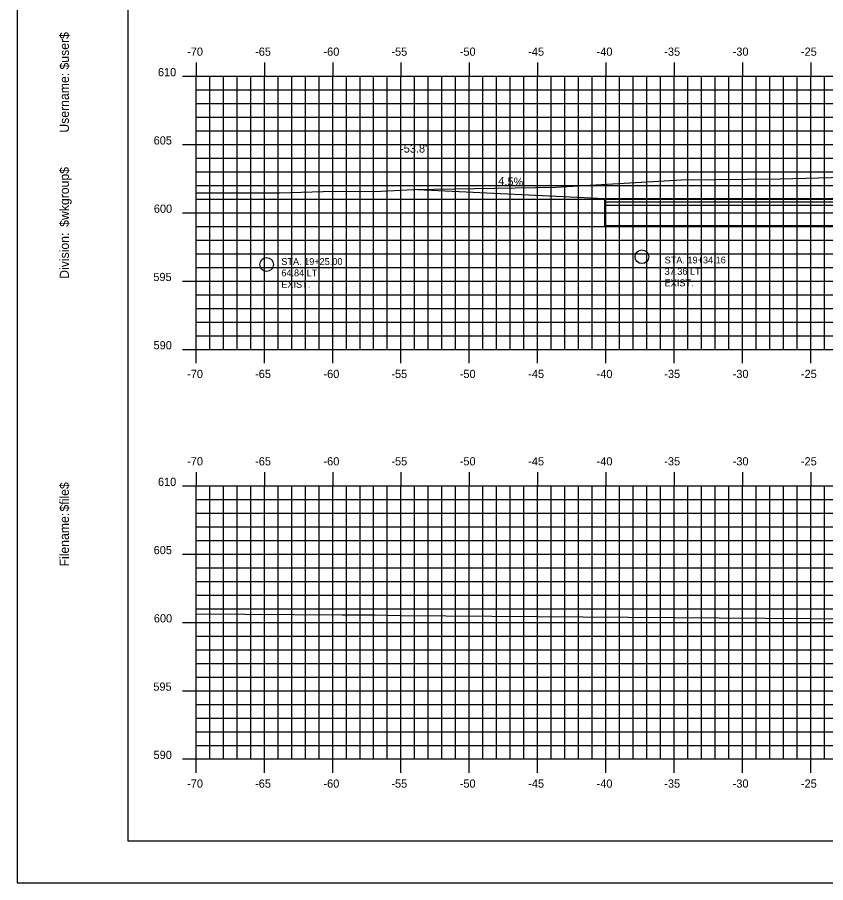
# Model space of a CAD drawing. Extents: x 1048141 to 1048311, y 780904 to 781014.
# Drawn here: x 1048140.6 to 1048199.8, y 780904.1 to 780967.4 of the extents above; entities that cross this region are included whole.
import ezdxf

# ---------------------------------------------------------------- set-up
doc = ezdxf.new("R2010")
doc.units = 0
for name, color, linetype in [('ANNOTATION', 7, 'Continuous'), ('D_Roadway_Centerline', 7, 'Continuous'), ('D_Roadway_Edge_Pavement', 7, 'Continuous'), ('D_Roadway_Pavement', 7, 'Continuous'), ('D_Roadway_SlopeLines', 7, 'Continuous'), ('D_Roadway_SubGrade', 7, 'Continuous'), ('D_Text_Monospaced', 7, 'Continuous'), ('Default', 7, 'Continuous'), ('H_V ANNOTATION', 7, 'Continuous'), ('MAJOR', 7, 'Continuous'), ('MINOR', 7, 'Continuous'), ('S_Roadway_Centerline', 7, 'Continuous'), ('S_Utilities_UG_Water_Line', 7, 'Continuous')]:
    doc.layers.add(name, color=color, linetype=linetype)

msp = doc.modelspace()

# ---------------------------------------------------------------- linework, layer by layer
at = {"layer": 'D_Roadway_Centerline'}
msp.add_line((1048183.644, 780954.167), (1048183.644, 780954.167), dxfattribs=at)
msp.add_lwpolyline([(1048169.913, 780954.819), (1048183.644, 780954.167), (1048223.713, 780954.151), (1048293.713, 780953.171)], dxfattribs=at)
at = {"layer": 'D_Roadway_Edge_Pavement'}
msp.add_lwpolyline([(1048183.644, 780953.917), (1048183.644, 780954.167), (1048223.713, 780954.151), (1048293.713, 780953.171), (1048293.709, 780952.921), (1048223.713, 780953.901)], close=True, dxfattribs=at)
at = {"layer": 'D_Roadway_Pavement'}
msp.add_lwpolyline([(1048183.644, 780953.667), (1048183.644, 780953.917), (1048223.713, 780953.901), (1048293.709, 780952.921), (1048293.706, 780952.671), (1048223.713, 780953.651)], close=True, dxfattribs=at)
at = {"layer": 'D_Roadway_SlopeLines'}
msp.add_line((1048183.644, 780954.167), (1048183.644, 780954.167), dxfattribs=at)
at = {"layer": 'D_Roadway_SubGrade'}
msp.add_lwpolyline([(1048183.644, 780952.167), (1048183.644, 780953.667), (1048223.713, 780953.651), (1048293.706, 780952.671), (1048293.685, 780951.171), (1048223.713, 780952.151)], close=True, dxfattribs=at)
at = {"layer": 'Default'}
for p, q in [((1048148.713, 781012.114), (1048148.713, 780907.114)), ((1048223.712, 780952.151), (1048183.643, 780952.167)), ((1048148.713, 780907.114), (1048308.713, 780907.114))]:
    msp.add_line(p, q, dxfattribs=at)
msp.add_lwpolyline([(1048140.62, 780904.055), (1048310.62, 780904.055), (1048310.62, 781014.055), (1048140.62, 781014.055)], close=True, dxfattribs=at)
at = {"layer": 'MAJOR'}
for p, q in [((1048153.713, 780964.116), (1048153.713, 780963.114)), ((1048158.713, 780964.116), (1048158.713, 780963.114)), ((1048163.713, 780964.116), (1048163.713, 780963.114)), ((1048168.713, 780964.116), (1048168.713, 780963.114)), ((1048173.713, 780964.116), (1048173.713, 780963.114)), ((1048178.713, 780964.116), (1048178.713, 780963.114)), ((1048183.713, 780964.116), (1048183.713, 780963.114)), ((1048188.713, 780964.116), (1048188.713, 780963.114)), ((1048193.713, 780964.116), (1048193.713, 780963.114)), ((1048198.713, 780964.116), (1048198.713, 780963.114)), ((1048152.711, 780963.114), (1048153.713, 780963.114)), ((1048153.713, 780963.114), (1048293.713, 780963.114)), ((1048153.713, 780943.114), (1048153.713, 780963.114)), ((1048153.713, 780943.114), (1048153.713, 780963.114)), ((1048153.713, 780963.114), (1048293.713, 780963.114)), ((1048158.713, 780943.114), (1048158.713, 780963.114)), ((1048163.713, 780943.114), (1048163.713, 780963.114)), ((1048168.713, 780943.114), (1048168.713, 780963.114)), ((1048173.713, 780943.114), (1048173.713, 780963.114)), ((1048178.713, 780943.114), (1048178.713, 780963.114)), ((1048183.713, 780943.114), (1048183.713, 780963.114)), ((1048188.713, 780943.114), (1048188.713, 780963.114)), ((1048193.713, 780943.114), (1048193.713, 780963.114)), ((1048198.713, 780943.114), (1048198.713, 780963.114)), ((1048152.711, 780958.114), (1048153.713, 780958.114)), ((1048153.713, 780958.114), (1048293.713, 780958.114)), ((1048152.711, 780953.114), (1048153.713, 780953.114)), ((1048153.713, 780953.114), (1048293.713, 780953.114)), ((1048152.711, 780948.114), (1048153.713, 780948.114)), ((1048153.713, 780948.114), (1048293.713, 780948.114)), ((1048152.711, 780943.114), (1048153.713, 780943.114)), ((1048153.713, 780943.114), (1048293.713, 780943.114)), ((1048153.713, 780943.114), (1048293.713, 780943.114)), ((1048153.713, 780942.112), (1048153.713, 780943.114)), ((1048158.713, 780942.112), (1048158.713, 780943.114)), ((1048163.713, 780942.112), (1048163.713, 780943.114)), ((1048168.713, 780942.112), (1048168.713, 780943.114)), ((1048173.713, 780942.112), (1048173.713, 780943.114)), ((1048178.713, 780942.112), (1048178.713, 780943.114)), ((1048183.713, 780942.112), (1048183.713, 780943.114)), ((1048188.713, 780942.112), (1048188.713, 780943.114)), ((1048193.713, 780942.112), (1048193.713, 780943.114)), ((1048198.713, 780942.112), (1048198.713, 780943.114)), ((1048153.713, 780934.116), (1048153.713, 780933.114)), ((1048158.713, 780934.116), (1048158.713, 780933.114)), ((1048163.713, 780934.116), (1048163.713, 780933.114)), ((1048168.713, 780934.116), (1048168.713, 780933.114)), ((1048173.713, 780934.116), (1048173.713, 780933.114)), ((1048178.713, 780934.116), (1048178.713, 780933.114)), ((1048183.713, 780934.116), (1048183.713, 780933.114)), ((1048188.713, 780934.116), (1048188.713, 780933.114)), ((1048193.713, 780934.116), (1048193.713, 780933.114)), ((1048198.713, 780934.116), (1048198.713, 780933.114)), ((1048152.711, 780933.114), (1048153.713, 780933.114)), ((1048153.713, 780933.114), (1048293.713, 780933.114)), ((1048153.713, 780913.114), (1048153.713, 780933.114)), ((1048153.713, 780913.114), (1048153.713, 780933.114)), ((1048153.713, 780933.114), (1048293.713, 780933.114)), ((1048158.713, 780913.114), (1048158.713, 780933.114)), ((1048163.713, 780913.114), (1048163.713, 780933.114)), ((1048168.713, 780913.114), (1048168.713, 780933.114)), ((1048173.713, 780913.114), (1048173.713, 780933.114)), ((1048178.713, 780913.114), (1048178.713, 780933.114)), ((1048183.713, 780913.114), (1048183.713, 780933.114)), ((1048188.713, 780913.114), (1048188.713, 780933.114)), ((1048193.713, 780913.114), (1048193.713, 780933.114)), ((1048198.713, 780913.114), (1048198.713, 780933.114)), ((1048152.711, 780928.114), (1048153.713, 780928.114)), ((1048153.713, 780928.114), (1048293.713, 780928.114)), ((1048152.711, 780923.114), (1048153.713, 780923.114)), ((1048153.713, 780923.114), (1048293.713, 780923.114)), ((1048152.711, 780918.114), (1048153.713, 780918.114)), ((1048153.713, 780918.114), (1048293.713, 780918.114)), ((1048152.711, 780913.114), (1048153.713, 780913.114)), ((1048153.713, 780913.114), (1048293.713, 780913.114)), ((1048153.713, 780913.114), (1048293.713, 780913.114)), ((1048153.713, 780912.112), (1048153.713, 780913.114)), ((1048158.713, 780912.112), (1048158.713, 780913.114)), ((1048163.713, 780912.112), (1048163.713, 780913.114)), ((1048168.713, 780912.112), (1048168.713, 780913.114)), ((1048173.713, 780912.112), (1048173.713, 780913.114)), ((1048178.713, 780912.112), (1048178.713, 780913.114)), ((1048183.713, 780912.112), (1048183.713, 780913.114)), ((1048188.713, 780912.112), (1048188.713, 780913.114)), ((1048193.713, 780912.112), (1048193.713, 780913.114)), ((1048198.713, 780912.112), (1048198.713, 780913.114))]:
    msp.add_line(p, q, dxfattribs=at)
at = {"layer": 'MINOR'}
for p, q in [((1048154.713, 780943.114), (1048154.713, 780963.114)), ((1048155.713, 780943.114), (1048155.713, 780963.114)), ((1048156.713, 780943.114), (1048156.713, 780963.114)), ((1048157.713, 780943.114), (1048157.713, 780963.114)), ((1048159.713, 780943.114), (1048159.713, 780963.114)), ((1048160.713, 780943.114), (1048160.713, 780963.114)), ((1048161.713, 780943.114), (1048161.713, 780963.114)), ((1048162.713, 780943.114), (1048162.713, 780963.114)), ((1048164.713, 780943.114), (1048164.713, 780963.114)), ((1048165.713, 780943.114), (1048165.713, 780963.114)), ((1048166.713, 780943.114), (1048166.713, 780963.114)), ((1048167.713, 780943.114), (1048167.713, 780963.114)), ((1048169.713, 780943.114), (1048169.713, 780963.114)), ((1048170.713, 780943.114), (1048170.713, 780963.114)), ((1048171.713, 780943.114), (1048171.713, 780963.114)), ((1048172.713, 780943.114), (1048172.713, 780963.114)), ((1048174.713, 780943.114), (1048174.713, 780963.114)), ((1048175.713, 780943.114), (1048175.713, 780963.114)), ((1048176.713, 780943.114), (1048176.713, 780963.114)), ((1048177.713, 780943.114), (1048177.713, 780963.114)), ((1048179.713, 780943.114), (1048179.713, 780963.114)), ((1048180.713, 780943.114), (1048180.713, 780963.114)), ((1048181.713, 780943.114), (1048181.713, 780963.114)), ((1048182.713, 780943.114), (1048182.713, 780963.114)), ((1048184.713, 780943.114), (1048184.713, 780963.114)), ((1048185.713, 780943.114), (1048185.713, 780963.114)), ((1048186.713, 780943.114), (1048186.713, 780963.114)), ((1048187.713, 780943.114), (1048187.713, 780963.114)), ((1048189.713, 780943.114), (1048189.713, 780963.114)), ((1048190.713, 780943.114), (1048190.713, 780963.114)), ((1048191.713, 780943.114), (1048191.713, 780963.114)), ((1048192.713, 780943.114), (1048192.713, 780963.114)), ((1048194.713, 780943.114), (1048194.713, 780963.114)), ((1048195.713, 780943.114), (1048195.713, 780963.114)), ((1048196.713, 780943.114), (1048196.713, 780963.114)), ((1048197.713, 780943.114), (1048197.713, 780963.114)), ((1048199.713, 780943.114), (1048199.713, 780963.114)), ((1048153.713, 780962.114), (1048293.713, 780962.114)), ((1048153.713, 780962.114), (1048154.715, 780962.114)), ((1048153.713, 780961.114), (1048293.713, 780961.114)), ((1048153.713, 780961.114), (1048154.715, 780961.114)), ((1048153.713, 780960.114), (1048293.713, 780960.114)), ((1048153.713, 780960.114), (1048154.715, 780960.114)), ((1048153.713, 780959.114), (1048293.713, 780959.114)), ((1048153.713, 780959.114), (1048154.715, 780959.114)), ((1048153.713, 780957.114), (1048293.713, 780957.114)), ((1048153.713, 780957.114), (1048154.715, 780957.114)), ((1048153.713, 780956.114), (1048293.713, 780956.114)), ((1048153.713, 780956.114), (1048154.715, 780956.114)), ((1048153.713, 780955.114), (1048293.713, 780955.114)), ((1048153.713, 780955.114), (1048154.715, 780955.114)), ((1048153.713, 780954.114), (1048293.713, 780954.114)), ((1048153.713, 780954.114), (1048154.715, 780954.114)), ((1048153.713, 780952.114), (1048293.713, 780952.114)), ((1048153.713, 780952.114), (1048154.715, 780952.114)), ((1048153.713, 780951.114), (1048293.713, 780951.114)), ((1048153.713, 780951.114), (1048154.715, 780951.114)), ((1048153.713, 780950.114), (1048293.713, 780950.114)), ((1048153.713, 780950.114), (1048154.715, 780950.114)), ((1048153.713, 780949.114), (1048293.713, 780949.114)), ((1048153.713, 780949.114), (1048154.715, 780949.114)), ((1048153.713, 780947.114), (1048293.713, 780947.114)), ((1048153.713, 780947.114), (1048154.715, 780947.114)), ((1048153.713, 780946.114), (1048293.713, 780946.114)), ((1048153.713, 780946.114), (1048154.715, 780946.114)), ((1048153.713, 780945.114), (1048293.713, 780945.114)), ((1048153.713, 780945.114), (1048154.715, 780945.114)), ((1048153.713, 780944.114), (1048293.713, 780944.114)), ((1048153.713, 780944.114), (1048154.715, 780944.114)), ((1048154.713, 780913.114), (1048154.713, 780933.114)), ((1048155.713, 780913.114), (1048155.713, 780933.114)), ((1048156.713, 780913.114), (1048156.713, 780933.114)), ((1048157.713, 780913.114), (1048157.713, 780933.114)), ((1048159.713, 780913.114), (1048159.713, 780933.114)), ((1048160.713, 780913.114), (1048160.713, 780933.114)), ((1048161.713, 780913.114), (1048161.713, 780933.114)), ((1048162.713, 780913.114), (1048162.713, 780933.114)), ((1048164.713, 780913.114), (1048164.713, 780933.114)), ((1048165.713, 780913.114), (1048165.713, 780933.114)), ((1048166.713, 780913.114), (1048166.713, 780933.114)), ((1048167.713, 780913.114), (1048167.713, 780933.114)), ((1048169.713, 780913.114), (1048169.713, 780933.114)), ((1048170.713, 780913.114), (1048170.713, 780933.114)), ((1048171.713, 780913.114), (1048171.713, 780933.114)), ((1048172.713, 780913.114), (1048172.713, 780933.114)), ((1048174.713, 780913.114), (1048174.713, 780933.114)), ((1048175.713, 780913.114), (1048175.713, 780933.114)), ((1048176.713, 780913.114), (1048176.713, 780933.114)), ((1048177.713, 780913.114), (1048177.713, 780933.114)), ((1048179.713, 780913.114), (1048179.713, 780933.114)), ((1048180.713, 780913.114), (1048180.713, 780933.114)), ((1048181.713, 780913.114), (1048181.713, 780933.114)), ((1048182.713, 780913.114), (1048182.713, 780933.114)), ((1048184.713, 780913.114), (1048184.713, 780933.114)), ((1048185.713, 780913.114), (1048185.713, 780933.114)), ((1048186.713, 780913.114), (1048186.713, 780933.114)), ((1048187.713, 780913.114), (1048187.713, 780933.114)), ((1048189.713, 780913.114), (1048189.713, 780933.114)), ((1048190.713, 780913.114), (1048190.713, 780933.114)), ((1048191.713, 780913.114), (1048191.713, 780933.114)), ((1048192.713, 780913.114), (1048192.713, 780933.114)), ((1048194.713, 780913.114), (1048194.713, 780933.114)), ((1048195.713, 780913.114), (1048195.713, 780933.114)), ((1048196.713, 780913.114), (1048196.713, 780933.114)), ((1048197.713, 780913.114), (1048197.713, 780933.114)), ((1048199.713, 780913.114), (1048199.713, 780933.114)), ((1048153.713, 780932.114), (1048293.713, 780932.114)), ((1048153.713, 780932.114), (1048154.715, 780932.114)), ((1048153.713, 780931.114), (1048293.713, 780931.114)), ((1048153.713, 780931.114), (1048154.715, 780931.114)), ((1048153.713, 780930.114), (1048293.713, 780930.114)), ((1048153.713, 780930.114), (1048154.715, 780930.114)), ((1048153.713, 780929.114), (1048293.713, 780929.114)), ((1048153.713, 780929.114), (1048154.715, 780929.114)), ((1048153.713, 780927.114), (1048293.713, 780927.114)), ((1048153.713, 780927.114), (1048154.715, 780927.114)), ((1048153.713, 780926.114), (1048293.713, 780926.114)), ((1048153.713, 780926.114), (1048154.715, 780926.114)), ((1048153.713, 780925.114), (1048293.713, 780925.114)), ((1048153.713, 780925.114), (1048154.715, 780925.114)), ((1048153.713, 780924.114), (1048293.713, 780924.114)), ((1048153.713, 780924.114), (1048154.715, 780924.114)), ((1048153.713, 780922.114), (1048293.713, 780922.114)), ((1048153.713, 780922.114), (1048154.715, 780922.114)), ((1048153.713, 780921.114), (1048293.713, 780921.114)), ((1048153.713, 780921.114), (1048154.715, 780921.114)), ((1048153.713, 780920.114), (1048293.713, 780920.114)), ((1048153.713, 780920.114), (1048154.715, 780920.114)), ((1048153.713, 780919.114), (1048293.713, 780919.114)), ((1048153.713, 780919.114), (1048154.715, 780919.114)), ((1048153.713, 780917.114), (1048293.713, 780917.114)), ((1048153.713, 780917.114), (1048154.715, 780917.114)), ((1048153.713, 780916.114), (1048293.713, 780916.114)), ((1048153.713, 780916.114), (1048154.715, 780916.114)), ((1048153.713, 780915.114), (1048293.713, 780915.114)), ((1048153.713, 780915.114), (1048154.715, 780915.114)), ((1048153.713, 780914.114), (1048293.713, 780914.114)), ((1048153.713, 780914.114), (1048154.715, 780914.114))]:
    msp.add_line(p, q, dxfattribs=at)
at = {"layer": 'S_Roadway_Centerline'}
for points in [[(1048153.713, 780954.572), (1048159.825, 780954.58), (1048163.027, 780954.664), (1048167.266, 780954.693), (1048169.627, 780954.814), (1048180.042, 780954.995), (1048189.22, 780955.536), (1048196.477, 780955.609), (1048205.851, 780955.838), (1048213.438, 780955.489), (1048227.587, 780955.088), (1048240.634, 780954.526), (1048248.544, 780954.12), (1048264.413, 780953.312), (1048264.419, 780953.312), (1048264.422, 780953.313), (1048264.434, 780953.311), (1048276.919, 780952.999), (1048290.846, 780952.301), (1048293.713, 780952.036)], [(1048153.713, 780923.736), (1048164.413, 780923.663), (1048165.392, 780923.664), (1048166.788, 780923.659), (1048168.702, 780923.63), (1048218.665, 780923.246), (1048221.263, 780923.212), (1048270.425, 780922.704), (1048273.522, 780922.631), (1048273.524, 780922.634), (1048293.713, 780922.409)]]:
    msp.add_lwpolyline(points, dxfattribs=at)
at = {"layer": 'S_Utilities_UG_Water_Line'}
for centre in [(1048186.352, 780949.896), (1048158.877, 780949.327)]:
    msp.add_circle(centre, 0.501, dxfattribs=at)

# ---------------------------------------------------------------- texts
at = {"layer": 'ANNOTATION'}
for s, rotation, p in [("-53.8'", 360, (1048168.647, 780957.519)), ('4.5%', 357.22134, (1048175.826, 780955.156))]:
    msp.add_text(s, height=0.6, rotation=rotation, dxfattribs=at).set_placement(p)
at = {"layer": 'D_Text_Monospaced'}
for s, height, p in [('STA. 19+25.00', 0.49998, (1048159.951, 780949.294)), ('STA. 19+34.16', 0.49998, (1048188.018, 780949.406)), ('64.84 LT.', 0.5, (1048159.951, 780948.46)), ('37.36 LT.', 0.5, (1048188.018, 780948.572)), ('EXIST. ', 0.5, (1048159.951, 780947.62)), ('EXIST. ', 0.5, (1048188.018, 780947.732))]:
    msp.add_text(s, height=height, dxfattribs=at).set_placement(p)
at = {"layer": 'Default'}
for s, p in [('$user$', (1048144.398, 780963.606)), ('Username:', (1048144.398, 780958.982)), ('$wkgroup$', (1048144.398, 780952.084)), ('Division:', (1048144.398, 780948.28)), ('$file$', (1048144.398, 780931.24)), ('Filename:', (1048144.398, 780927.213))]:
    msp.add_text(s, height=0.6696, rotation=90, dxfattribs=at).set_placement(p)
at = {"layer": 'H_V ANNOTATION'}
for s, p in [('-70', (1048153.055, 780964.614)), ('-65', (1048158.031, 780964.614)), ('-60', (1048163.039, 780964.614)), ('-55', (1048168.009, 780964.614)), ('-50', (1048173.017, 780964.614)), ('-45', (1048178.031, 780964.614)), ('-40', (1048183.039, 780964.614)), ('-35', (1048187.993, 780964.614)), ('-30', (1048193.001, 780964.614)), ('-25', (1048197.998, 780964.614)), ('610', (1048150.918, 780963.114)), ('605', (1048150.602, 780958.114)), ('600', (1048150.618, 780953.114)), ('595', (1048150.58, 780948.114)), ('590', (1048150.596, 780943.114)), ('-70', (1048153.055, 780941.014)), ('-65', (1048158.031, 780941.014)), ('-60', (1048163.039, 780941.014)), ('-55', (1048168.009, 780941.014)), ('-50', (1048173.017, 780941.014)), ('-45', (1048178.031, 780941.014)), ('-40', (1048183.039, 780941.014)), ('-35', (1048187.993, 780941.014)), ('-30', (1048193.001, 780941.014)), ('-25', (1048197.998, 780941.014)), ('-70', (1048153.055, 780934.614)), ('-65', (1048158.031, 780934.614)), ('-60', (1048163.039, 780934.614)), ('-55', (1048168.009, 780934.614)), ('-50', (1048173.017, 780934.614)), ('-45', (1048178.031, 780934.614)), ('-40', (1048183.039, 780934.614)), ('-35', (1048187.993, 780934.614)), ('-30', (1048193.001, 780934.614)), ('-25', (1048197.998, 780934.614)), ('610', (1048150.918, 780933.114)), ('605', (1048150.602, 780928.114)), ('600', (1048150.618, 780923.114)), ('595', (1048150.58, 780918.114)), ('590', (1048150.596, 780913.114)), ('-70', (1048153.055, 780911.014)), ('-65', (1048158.031, 780911.014)), ('-60', (1048163.039, 780911.014)), ('-55', (1048168.009, 780911.014)), ('-50', (1048173.017, 780911.014)), ('-45', (1048178.031, 780911.014)), ('-40', (1048183.039, 780911.014)), ('-35', (1048187.993, 780911.014)), ('-30', (1048193.001, 780911.014)), ('-25', (1048197.998, 780911.014))]:
    msp.add_text(s, height=0.6, dxfattribs=at).set_placement(p)
at = {"layer": 'MAJOR'}
for p in [(1048153.708, 780943.114), (1048153.708, 780913.114)]:
    msp.add_text('-', height=0.006, dxfattribs=at).set_placement(p)
at = {"layer": 'S_Roadway_Centerline'}
for s, p in [('L', (1048189.212, 780955.528)), ('C', (1048189.215, 780955.536))]:
    msp.add_text(s, height=0.0146, dxfattribs=at).set_placement(p)

doc.saveas('drawing.dxf')
